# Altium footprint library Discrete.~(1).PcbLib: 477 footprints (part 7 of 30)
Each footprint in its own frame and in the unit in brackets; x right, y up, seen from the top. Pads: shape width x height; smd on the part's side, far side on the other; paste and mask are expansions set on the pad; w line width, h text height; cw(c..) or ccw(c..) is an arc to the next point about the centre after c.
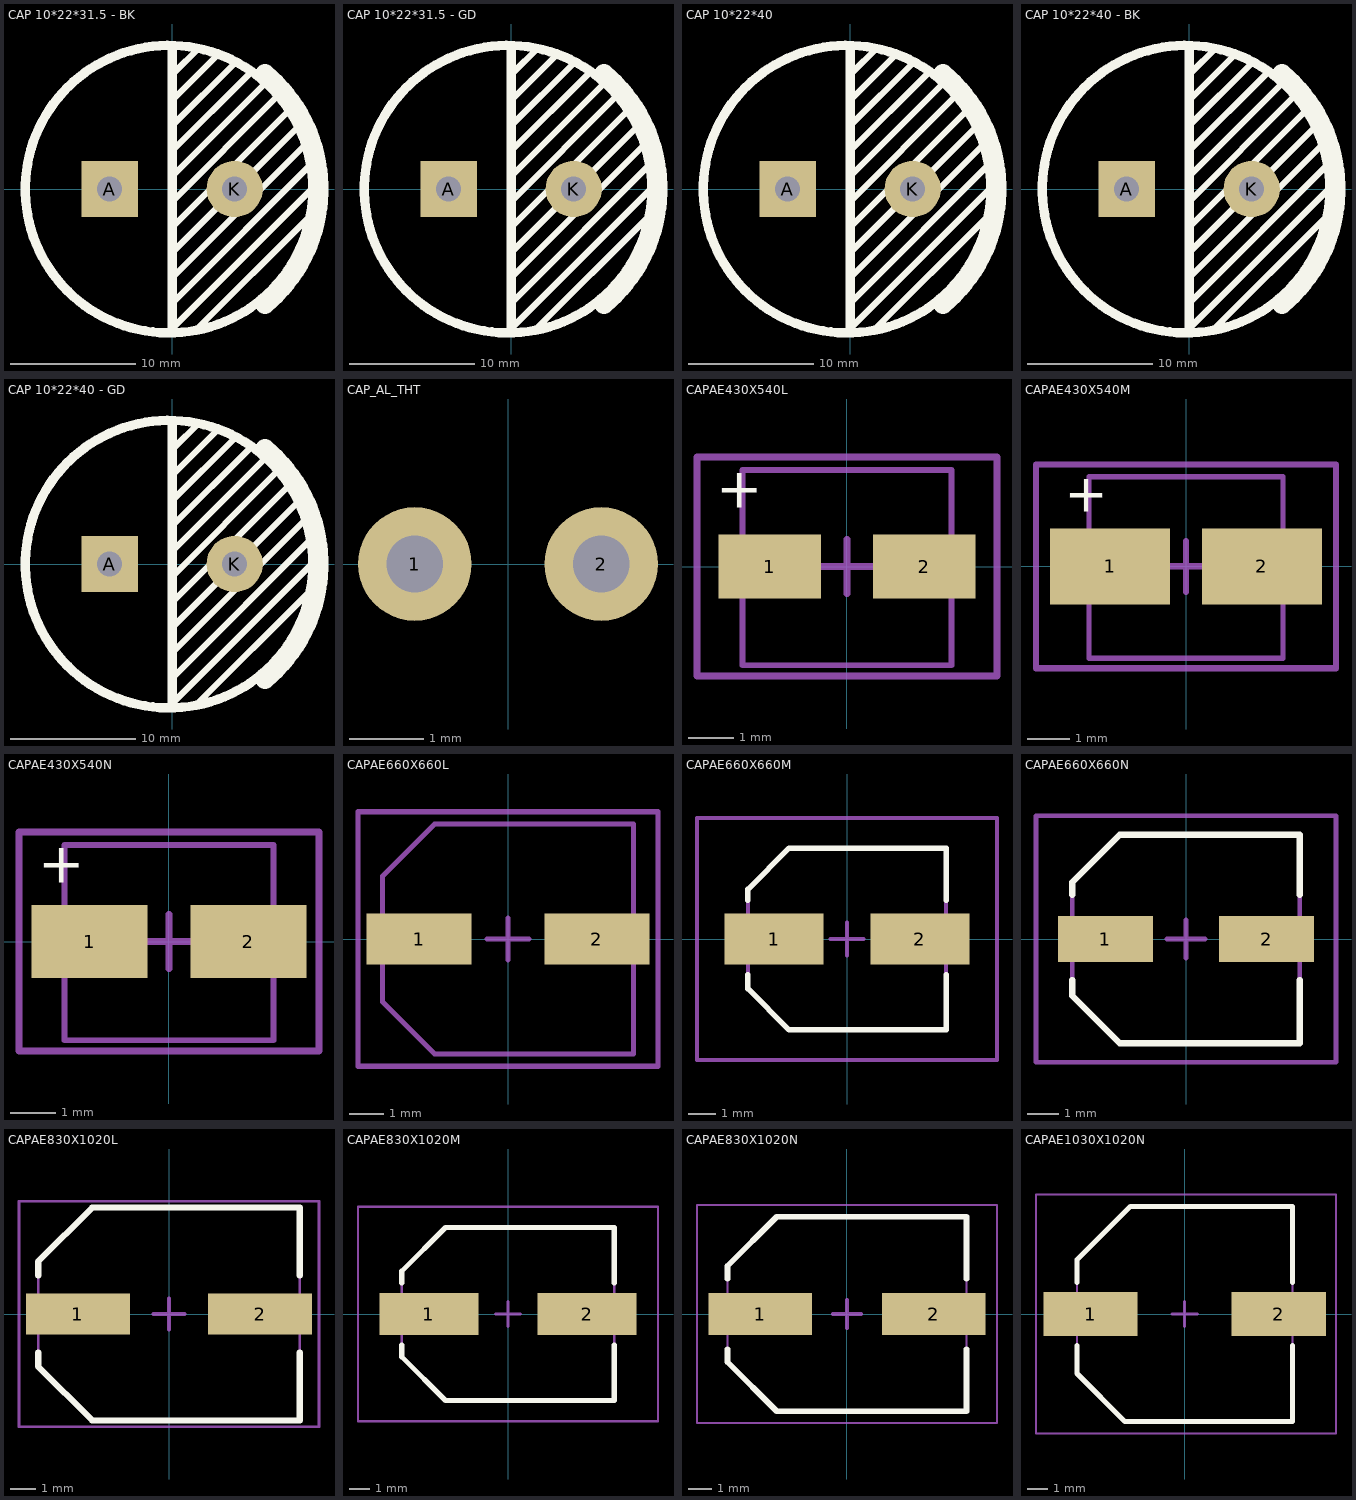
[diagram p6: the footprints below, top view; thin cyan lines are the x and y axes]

## CAP 10*22*31.5 - BK [mm] "脚距10mm直径22mm高度31.5mm"
pads (2):
  rect 4.5x4.5 hole 2: A(-5,0)
  round 4.5 hole 2: K(5,0)
Top Overlay:
  circle w0.754: c-0.248,-0.013 r11.5
  lines w0.504: 0,-7.112 10.541,3.429 ; 0,-5.08 10.033,4.953 ; 0,-3.048 9.271,6.223 ; 0,-1.016 8.382,7.366 ; 0,1.016 7.493,8.509 ; 0,3.048 6.223,9.271 ; 0,5.08 4.953,10.033 ; 0,7.112 3.556,10.668 ; 0.254,-10.922 11.43,0.254 ; 0.254,-8.89 11.43,2.286 ; 0.254,9.398 2.032,11.176 ; 1.778,-11.43 11.049,-2.159
  lines w0.754: 0,-11.25 0,11.25
  lines w1.524: 7.428,-9.219 ccw(c-0.254,0) 7.428,9.219
3D body "CAP 10X22X31.5.STEP": height 31.54, standoff -3.37, extent -11,-10.997 11.01,10.997

## CAP 10*22*31.5 - GD [mm] "脚距10mm直径22mm高度31.5mm"
pads (2):
  rect 4.5x4.5 hole 2: A(-5,0)
  round 4.5 hole 2: K(5,0)
Top Overlay:
  circle w0.754: c-0.248,-0.013 r11.5
  lines w0.504: 0,-7.112 10.541,3.429 ; 0,-5.08 10.033,4.953 ; 0,-3.048 9.271,6.223 ; 0,-1.016 8.382,7.366 ; 0,1.016 7.493,8.509 ; 0,3.048 6.223,9.271 ; 0,5.08 4.953,10.033 ; 0,7.112 3.556,10.668 ; 0.254,-10.922 11.43,0.254 ; 0.254,-8.89 11.43,2.286 ; 0.254,9.398 2.032,11.176 ; 1.778,-11.43 11.049,-2.159
  lines w0.754: 0,-11.25 0,11.25
  lines w1.524: 7.428,-9.219 ccw(c-0.254,0) 7.428,9.219
3D body "CAP 10X22X31.5.STEP": height 31.54, standoff -3.37, extent -11,-10.997 11.01,10.997

## CAP 10*22*40 [mm] "脚距10mm直径22mm高度40mm"
pads (2):
  rect 4.5x4.5 hole 2: A(-5,0)
  round 4.5 hole 2: K(5,0)
Top Overlay:
  circle w0.754: c-0.248,-0.013 r11.5
  lines w0.504: 0,-7.112 10.541,3.429 ; 0,-5.08 10.033,4.953 ; 0,-3.048 9.271,6.223 ; 0,-1.016 8.382,7.366 ; 0,1.016 7.493,8.509 ; 0,3.048 6.223,9.271 ; 0,5.08 4.953,10.033 ; 0,7.112 3.556,10.668 ; 0.254,-10.922 11.43,0.254 ; 0.254,-8.89 11.43,2.286 ; 0.254,9.398 2.032,11.176 ; 1.778,-11.43 11.049,-2.159
  lines w0.754: 0,-11.25 0,11.25
  lines w1.524: 7.428,-9.219 ccw(c-0.254,0) 7.428,9.219
3D body "CAP 10X22X40.STEP": height 40.03, standoff -3.38, extent -11,-10.999 11.01,10.999

## CAP 10*22*40 - BK [mm] "脚距10mm直径22mm高度40mm"
pads (2):
  rect 4.5x4.5 hole 2: A(-5,0)
  round 4.5 hole 2: K(5,0)
Top Overlay:
  circle w0.754: c-0.248,-0.013 r11.5
  lines w0.504: 0,-7.112 10.541,3.429 ; 0,-5.08 10.033,4.953 ; 0,-3.048 9.271,6.223 ; 0,-1.016 8.382,7.366 ; 0,1.016 7.493,8.509 ; 0,3.048 6.223,9.271 ; 0,5.08 4.953,10.033 ; 0,7.112 3.556,10.668 ; 0.254,-10.922 11.43,0.254 ; 0.254,-8.89 11.43,2.286 ; 0.254,9.398 2.032,11.176 ; 1.778,-11.43 11.049,-2.159
  lines w0.754: 0,-11.25 0,11.25
  lines w1.524: 7.428,-9.219 ccw(c-0.254,0) 7.428,9.219
3D body "CAP 10X22X40.STEP": height 40.04, standoff -3.37, extent -11,-10.999 11.01,10.999

## CAP 10*22*40 - GD [mm] "脚距10mm直径22mm高度40mm"
pads (2):
  rect 4.5x4.5 hole 2: A(-5,0)
  round 4.5 hole 2: K(5,0)
Top Overlay:
  circle w0.754: c-0.248,-0.013 r11.5
  lines w0.504: 0,-7.112 10.541,3.429 ; 0,-5.08 10.033,4.953 ; 0,-3.048 9.271,6.223 ; 0,-1.016 8.382,7.366 ; 0,1.016 7.493,8.509 ; 0,3.048 6.223,9.271 ; 0,5.08 4.953,10.033 ; 0,7.112 3.556,10.668 ; 0.254,-10.922 11.43,0.254 ; 0.254,-8.89 11.43,2.286 ; 0.254,9.398 2.032,11.176 ; 1.778,-11.43 11.049,-2.159
  lines w0.754: 0,-11.25 0,11.25
  lines w1.524: 7.428,-9.219 ccw(c-0.254,0) 7.428,9.219
3D body "CAP 10X22X40.STEP": height 40.04, standoff -3.37, extent -11,-10.999 11.01,10.999

## CAP_AL_THT [mil] "6mm diameter"
height 433.07
pads (2):
  round 60 hole 30: 1(-49.21,0) 2(49.21,0)

## CAPAE430X540L [mm]
height 6
pads (2):
  rect 2.25x1.4 smd: 1(-1.7,0) 2(1.7,0)
Top Overlay:
  text "+" at -2.873,1 h1.52
Mechanical 13:
  lines w0.127: -2.3,-2.175 -2.3,2.125 2.3,2.125 2.3,-2.175 -2.3,-2.175
Mechanical 15:
  lines w0.076: -0.508,0 0.508,0 ; 0,-0.508 0,0.508
  lines w0.15: -0.6,0 0.6,0 ; 0,-0.6 0,0.6 ; -3.302,-2.413 3.302,-2.413 3.302,2.413 -3.302,2.413 -3.302,-2.413
3D body "CM B(4X5.4).STEP": height 5.4, standoff -0.01, extent -2.3,-2.175 2.3,2.125

## CAPAE430X540M [mm]
height 6
pads (2):
  rect 2.85x1.8 smd: 1(-1.8,0) 2(1.8,0)
Top Overlay:
  text "+" at -2.873,1 h1.52
Mechanical 13:
  lines w0.127: -2.3,-2.175 -2.3,2.125 2.3,2.125 2.3,-2.175 -2.3,-2.175
Mechanical 15:
  lines w0.076: -0.508,0 0.508,0 ; 0,-0.508 0,0.508
  lines w0.15: -0.6,0 0.6,0 ; 0,-0.6 0,0.6 ; -3.556,-2.413 3.556,-2.413 3.556,2.413 -3.556,2.413 -3.556,-2.413
3D body "CM B(4X5.4).STEP": height 5.4, standoff -0.01, extent -2.3,-2.175 2.3,2.125

## CAPAE430X540N [mm]
height 6
pads (2):
  rect 2.55x1.6 smd: 1(-1.75,0) 2(1.75,0)
Top Overlay:
  text "+" at -2.873,1 h1.52
Mechanical 13:
  lines w0.127: -2.3,-2.175 -2.3,2.125 2.3,2.125 2.3,-2.175 -2.3,-2.175
Mechanical 15:
  lines w0.076: -0.508,0 0.508,0 ; 0,-0.508 0,0.508
  lines w0.15: -0.6,0 0.6,0 ; 0,-0.6 0,0.6 ; -3.302,-2.413 3.302,-2.413 3.302,2.413 -3.302,2.413 -3.302,-2.413
3D body "CM B(4X5.4).STEP": height 5.4, standoff -0.01, extent -2.3,-2.175 2.3,2.125

## CAPAE660X660L [mm]
height 6
pads (2):
  rect 3x1.45 smd: 1(-2.55,0) 2(2.55,0)
Mechanical 13:
  lines w0.15: -3.6,-1.8 -3.6,1.8 -2.1,3.3 3.6,3.3 3.6,-3.3 -2.1,-3.3 -3.6,-1.8
Mechanical 15:
  lines w0.15: -0.6,0 0.6,0 ; 0,-0.6 0,0.6 ; -4.3,-3.65 4.3,-3.65 4.3,3.65 -4.3,3.65 -4.3,-3.65
3D body "CT 6X6-C.STEP": height 6, standoff -0.01, extent -3.5,-3.15 3.5,3.15

## CAPAE660X660M [mm]
height 6
pads (2):
  rect 3.6x1.85 smd: 1(-2.65,0) 2(2.65,0)
Top Overlay:
  lines w0.2: -3.6,-1.3 -3.6,-1.8 -2.1,-3.3 3.6,-3.3 ; -3.6,1.4 -3.6,1.8 -2.1,3.3 3.6,3.3 3.6,1.4 ; 3.6,-1.3 3.6,-3.3 ; 3.6,-3.3 3.6,-3.3
Mechanical 13:
  lines w0.15: 3.6,-3.3 -2.1,-3.3 -3.6,-1.8 -3.6,1.8 -2.1,3.3 3.6,3.3 3.6,-3.3 ; 3.6,-3.3 3.6,-3.3
Mechanical 15:
  lines w0.15: -0.6,0 0.6,0 ; 0,-0.6 0,0.6 ; -5.45,-4.4 5.45,-4.4 5.45,4.4 -5.45,4.4 -5.45,-4.4
3D body "CT 6X6-C.STEP": height 6, standoff -0.01, extent -3.5,-3.15 3.5,3.15

## CAPAE660X660N [mm]
height 6
pads (2):
  rect 3x1.45 smd: 1(-2.55,0) 2(2.55,0)
Top Overlay:
  lines w0.2: -3.6,-1.3 -3.6,-1.8 -2.1,-3.3 3.6,-3.3 ; -3.6,1.4 -3.6,1.8 -2.1,3.3 3.6,3.3 3.6,1.4 ; 3.6,-1.3 3.6,-3.3 ; 3.6,-3.3 3.6,-3.3
Mechanical 13:
  lines w0.15: 3.6,-3.3 3.6,3.3 -2.1,3.3 -3.6,1.8 -3.6,-1.8 -2.1,-3.3 3.6,-3.3 ; 3.6,-3.3 3.6,-3.3
Mechanical 15:
  lines w0.15: -0.6,0 0.6,0 ; 0,-0.6 0,0.6 ; -4.75,-3.9 4.75,-3.9 4.75,3.9 -4.75,3.9 -4.75,-3.9
3D body "CT 6X6-C.STEP": height 6, standoff -0.01, extent -3.5,-3.15 3.5,3.15

## CAPAE830X1020L [mm]
height 6
pads (2):
  rect 4.05x1.6 smd: 1(-3.55,0) 2(3.55,0)
Top Overlay:
  lines w0.245: -5.1,-1.5 -5.1,-2.05 -3,-4.15 5.1,-4.15 5.1,-1.5 ; -5.1,1.5 -5.1,2.05 -3,4.15 5.1,4.15 ; 5.1,1.5 5.1,4.15 ; 5.1,4.15 5.1,4.15
Mechanical 13:
  lines w0.1: -5.1,-0.55 -5.1,-0.5 ; -5.1,-2.05 -3,-4.15 ; -5.1,-2.05 -3,-4.15 ; -5.1,-2.05 -5.1,2.05 -3,4.15 5.1,4.15 5.1,-4.15 -3,-4.15
Mechanical 15:
  lines w0.1: -5.85,-4.4 5.85,-4.4 5.85,4.4 -5.85,4.4 -5.85,-4.4
  lines w0.15: -0.6,0 0.6,0 ; 0,-0.6 0,0.6
3D body "CT 10X8-V.STEP": height 8, standoff -0.01, extent -5.8,-5.15 5.8,5.15

## CAPAE830X1020M [mm]
height 6
pads (2):
  rect 4.75x2 smd: 1(-3.8,0) 2(3.8,0)
Top Overlay:
  lines w0.245: -5.1,-1.5 -5.1,-2.05 -3,-4.15 5.1,-4.15 5.1,-1.5 ; -5.1,1.5 -5.1,2.05 -3,4.15 5.1,4.15 ; 5.1,1.5 5.1,4.15 ; 5.1,4.15 5.1,4.15
Mechanical 13:
  lines w0.1: -5.1,-0.55 -5.1,-0.5 ; -5.1,-2.05 -3,-4.15 ; -5.1,-2.05 -3,-4.15 ; -5.1,-2.05 -5.1,2.05 -3,4.15 5.1,4.15 5.1,-4.15 -3,-4.15
Mechanical 15:
  lines w0.1: -7.2,-5.15 -7.2,5.15 7.2,5.15 7.2,-5.15 -7.2,-5.15
  lines w0.15: -0.6,0 0.6,0 ; 0,-0.6 0,0.6
3D body "CT 10X8-V.STEP": height 8, standoff -0.01, extent -5.8,-5.15 5.8,5.15

## CAPAE830X1020N [mm]
height 6
pads (2):
  rect 4.4x1.8 smd: 1(-3.7,0) 2(3.7,0)
Top Overlay:
  lines w0.245: -5.1,-1.5 -5.1,-2.05 -3,-4.15 5.1,-4.15 5.1,-1.5 ; -5.1,1.5 -5.1,2.05 -3,4.15 5.1,4.15 ; 5.1,1.5 5.1,4.15 ; 5.1,4.15 5.1,4.15
Mechanical 13:
  lines w0.1: -5.1,-0.55 -5.1,-0.5 ; -5.1,-2.05 -3,-4.15 ; -5.1,-2.05 -3,-4.15 ; -5.1,-2.05 -5.1,2.05 -3,4.15 5.1,4.15 5.1,-4.15 -3,-4.15
Mechanical 15:
  lines w0.1: -6.4,-4.65 6.4,-4.65 6.4,4.65 -6.4,4.65 -6.4,-4.65
  lines w0.15: -0.6,0 0.6,0 ; 0,-0.6 0,0.6
3D body "CT 10X8-V.STEP": height 8, standoff -0.01, extent -5.8,-5.15 5.8,5.15

## CAPAE1030X1020N [mm]
height 6
pads (2):
  rect 4.5x2.1 smd: 1(-4.5,0) 2(4.5,0)
Top Overlay:
  lines w0.245: -5.15,-1.5 -5.15,-2.851 -2.851,-5.15 ; -5.15,1.5 -5.15,2.597 -2.597,5.15 5.15,5.15 5.15,1.5 ; -2.794,-5.15 -2.851,-5.15 ; 5.15,-1.5 5.15,-5.15 -2.851,-5.15
Mechanical 13:
  lines w0.1: -5.15,-2.851 -5.15,2.597 -2.597,5.15 5.15,5.15 5.15,-5.15 -2.851,-5.15 -5.15,-2.851
Mechanical 15:
  lines w0.1: -7.112,-5.715 -7.112,5.715 7.239,5.715 7.239,-5.715 -7.112,-5.715
  lines w0.15: -0.6,0 0.6,0 ; 0,-0.6 0,0.6
3D body: height 1, standoff 0, extent -5.15,-5.15 5.15,5.15
3D body: height 10, standoff 0, extent -4.994,-4.999 5,4.999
